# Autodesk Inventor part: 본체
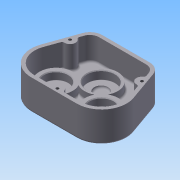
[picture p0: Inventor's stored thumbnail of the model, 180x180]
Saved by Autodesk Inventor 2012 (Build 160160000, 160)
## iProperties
Created: 2014-12
Part Number: 본체
Material: 알루미늄-6061
Document SubType Name: Modeling
Designer: Administrator
Density: 2.71 g/cm^3
Mass: 613.203 g
Surface Area: 668.767 cm^2
Volume: 226.274 cm^3
Author: Administrator
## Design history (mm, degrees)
sketch "스케치1"
  geometry: L1 (-47, 68.141)-(47, 68.141); L2 (-32.909, -36)-(32.909, -36); L3 (-47, 68.141)-(-66.85, 12.001); L4 (47, 68.141)-(66.85, 12.001); C1 r 24 at (0, 32.141); A1 r 46 centre (0, 32.141) between (-32.909, 0) and (32.909, 0); A2 r 36 centre (-32.909, 0) between (0, -14.595) and (0.317, -13.858); A3 r 36 centre (32.909, 0) between (-0.317, -13.858) and (0, -14.595); A4 r 36 centre (-32.909, 0) between (-66.85, 12.001) and (-32.909, -36); A5 r 36 centre (32.909, 0) between (32.909, -36) and (66.85, 12.001); 3 further points
  constraints: 12 point on circle, 8 end point, 6 centre point, 3 tangent, 3 vertical alignment, 2 horizontal alignment, 1 coincident, 1 horizontal, 1 midpoint, 1 parallel
  dimensions: "d0" = 94 distance of L1.start L1.end; "d2" = 48 diameter of C1; "d3" = 92 diameter of A1; "d4" = 36 distance from line of L1 C1.centre
extrude "돌출1" new body sketch "스케치1" distance "d5" = 44; taper "d6" = 0 deg
fillet "모깎기1" dims "d7" = 18
feature "쉘1" dims "d8" = 5
sketch "스케치2"
  geometry: L1 (0, 0)-(68.545, 0) reference; L2 (-27.863, -52.807)-(-12.256, -8.666) reference; L3 (67.181, -94.141)-(1.364, -94.141) reference; L4 (80.801, -8.666)-(96.408, -52.807) reference; A1 r 13 centre (68.545, -13) between (80.801, -8.666) and (68.545, 0) reference; A2 r 13 centre (0, -13) between (0, 0) and (-12.256, -8.666) reference; A3 r 31 centre (1.364, -63.141) between (-27.863, -52.807) and (1.364, -94.141) reference; A4 r 31 centre (67.181, -63.141) between (67.181, -94.141) and (96.408, -52.807) reference; 1 further point
extrude "돌출2" join sketch "스케치2" distance "d9" = 5; taper "d10" = 0 deg
sketch "스케치3"
  geometry: L1 (0, 5)-(68.545, 5) reference; L2 (67.181, -99.141)-(1.364, -99.141) reference; L3 (34.272, -31)-(34.272, -106.801); C1 r 24 at (34.272, -31); C2 r 24 at (1.364, -63.141); C3 r 24 at (67.181, -63.141); A1 r 46 centre (34.272, -31) between (1.364, -63.141) and (67.181, -63.141); 1 further point
  constraints: 4 centre point, 2 end point, 2 point on circle, 1 coincident, 1 equal radius, 1 horizontal alignment, 1 perpendicular, 1 vertical alignment
  dimensions: "d12" = 48 diameter of C1; "d13" = 36 distance from line of L3.start L1; "d142" = 92 diameter of A1; "d143" = 36 distance from line of L2 C3.centre; "d144" = 48 diameter of C2
extrude "돌출3" join sketch "스케치3" distance "d14" = 11; taper "d15" = 0 deg
sketch "스케치5"
  geometry: L1 (46.529, 54.474)-(62.136, 10.334) reference; L2 (32.909, -31)-(-32.909, -31) reference; L3 (-62.136, 10.334)-(-46.529, 54.474) reference; L4 (-34.272, 68.141)-(34.272, 68.141) reference; A1 r 8 centre (-51.95, 39.141) between (-54.617, 31.598) and (-49.284, 46.683); A2 r 8 centre (51.95, 39.141) between (49.284, 46.683) and (54.617, 31.598); A3 r 8 centre (0, -31) between (8, -31) and (-8, -31); 1 further point
  constraints: 8 point on line, 6 point on circle, 3 centre point, 1 equal radius, 1 horizontal alignment, 1 midpoint
  dimensions: "d19" = 16 diameter of A1; "d20" = 29 distance from line of A1.centre L4; "d21" = 16 diameter of A3
extrude "돌출5" join sketch "스케치5" stored distance "d22" = 7; taper "d23" = 0 deg
hole "구멍1" diameter "d30" = 4.134; stored, may be unused: countersink angle "d34" = 90 deg, drill point angle "d36" = 118 deg; dims "d28" = 10, "d29" = 10, "d31" = 20, "d32" = 4, "d33" = 2, "d35" = 23
hole "구멍2" diameter "d39" = 4.134; stored, may be unused: countersink angle "d43" = 90 deg, drill point angle "d45" = 118 deg; dims "d37" = 10, "d38" = 10, "d40" = 20, "d41" = 4, "d42" = 2, "d44" = 23
hole "구멍3" diameter "d48" = 4.134; stored, may be unused: countersink angle "d52" = 90 deg, drill point angle "d54" = 118 deg; dims "d46" = 10, "d47" = 10, "d49" = 20, "d50" = 4, "d51" = 2, "d53" = 23
hole "구멍4" diameter "d57" = 40; stored, may be unused: countersink angle "d61" = 90 deg, drill point angle "d63" = 0 deg; dims "d55" = 10, "d56" = 10, "d58" = 20, "d59" = 4, "d60" = 2, "d62" = 12
hole "구멍5" diameter "d66" = 20; stored, may be unused: countersink angle "d70" = 90 deg, drill point angle "d72" = 0 deg; dims "d64" = 10, "d65" = 10, "d67" = 20, "d68" = 4, "d69" = 2, "d71" = 3
hole "구멍6" diameter "d75" = 35; stored, may be unused: countersink angle "d79" = 90 deg, drill point angle "d81" = 0 deg; dims "d73" = 10, "d74" = 10, "d76" = 20, "d77" = 4, "d78" = 2, "d80" = 11
hole "구멍7" diameter "d84" = 35; stored, may be unused: countersink angle "d88" = 90 deg, drill point angle "d90" = 0 deg; dims "d82" = 10, "d83" = 10, "d85" = 20, "d86" = 4, "d87" = 2, "d89" = 11
sketch "스케치6"
  geometry: C1 r 17.5 at (-32.909, 0) reference; C2 r 17.5 at (32.909, 0) reference; C3 r 20 at (-32.909, 0); C4 r 20 at (32.909, 0); 1 further point
  constraints: 2 centre point, 1 equal radius
  dimensions: "d91" = 40 diameter of C3
extrude "돌출6" join sketch "스케치6" distance "d92" = 7; taper "d93" = -10 deg
hole "구멍8" diameter "d96" = 30; stored, may be unused: countersink angle "d100" = 90 deg, drill point angle "d102" = 0 deg; dims "d94" = 10, "d95" = 10, "d97" = 20, "d98" = 4, "d99" = 2, "d101" = 7
hole "구멍9" diameter "d105" = 30; stored, may be unused: countersink angle "d109" = 90 deg, drill point angle "d111" = 0 deg; dims "d103" = 10, "d104" = 10, "d106" = 20, "d107" = 4, "d108" = 2, "d110" = 7
hole "구멍10" diameter "d114" = 15.5; stored, may be unused: countersink angle "d118" = 90 deg, drill point angle "d120" = 0 deg; dims "d112" = 10, "d113" = 10, "d115" = 20, "d116" = 4, "d117" = 2, "d119" = 7
hole "구멍11" diameter "d123" = 15.5; stored, may be unused: countersink angle "d127" = 90 deg, drill point angle "d129" = 0 deg; dims "d121" = 10, "d122" = 10, "d124" = 20, "d125" = 4, "d126" = 2, "d128" = 7
sketch "스케치7"
  geometry: L1 (34.272, 68.141)-(-34.272, 68.141) reference; 2 further points
  constraints: 1 vertical alignment, 1 other
  dimensions: "d130" = 30 distance from line of point (0, 38.141) L1
feature "엠보싱1" sketch "스케치7" dims "d131" = 1, "d132" = 0
fillet "모깎기2" dims "d133" = 3
fillet "모깎기3" dims "d134" = 3
fillet "모깎기4" dims "d135" = 3
chamfer "모따기1" distance "d136" = 1; stored, may be unused: second distance "d137" = 2, angle "d138" = 45 deg
chamfer "모따기2" distance "d139" = 1; stored, may be unused: second distance "d140" = 2, angle "d141" = 45 deg
fillet "모깎기5" dims "d145" = 0.3
fillet "모깎기6" dims "d146" = 0.1
fillet "모깎기7" dims "d147" = 0.3
node "솔리드1"
other parameters: "d1" = 72
